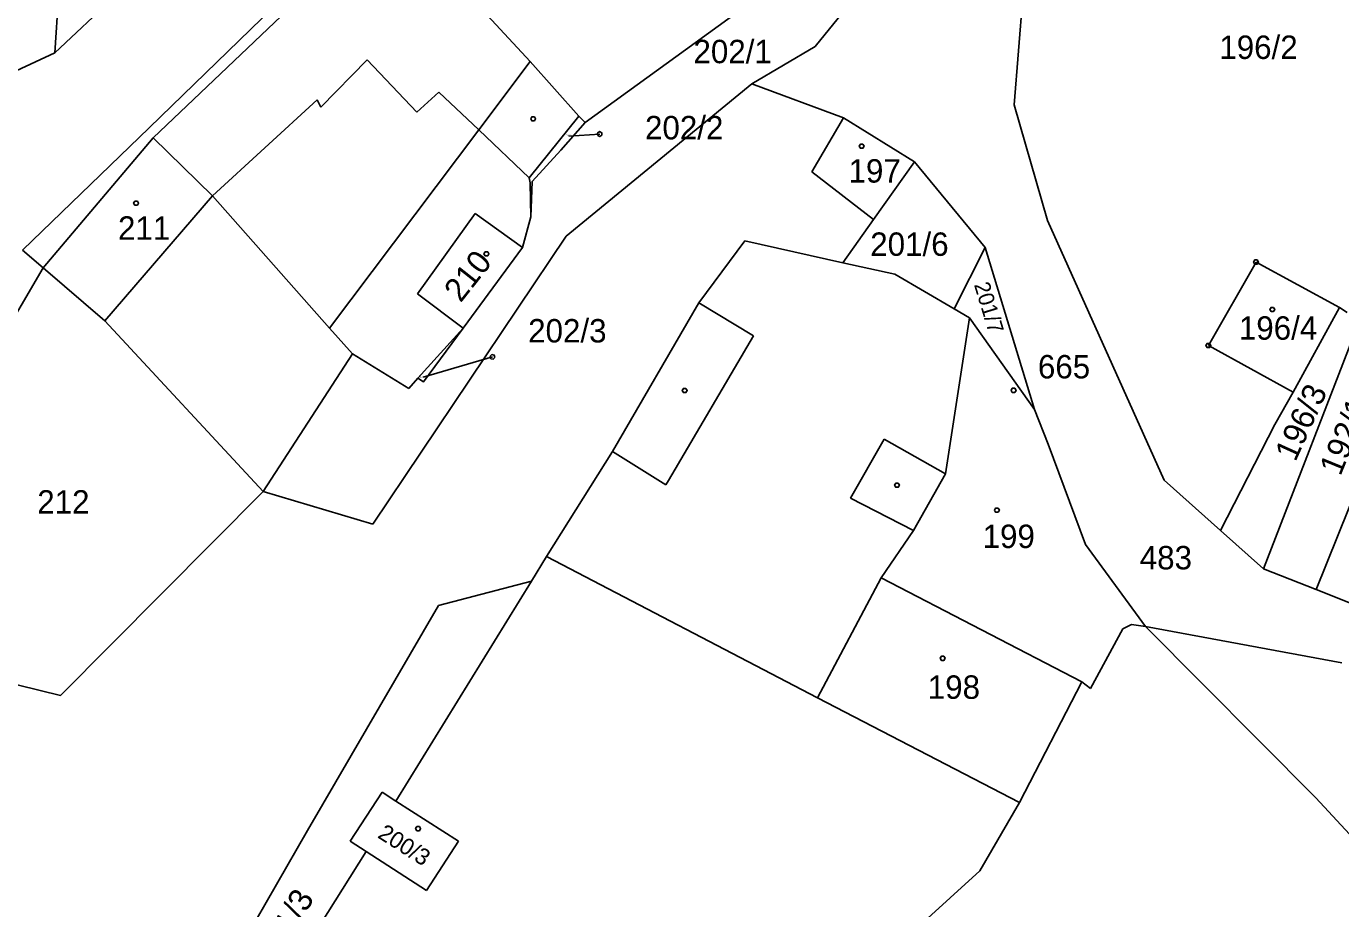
# Model space of a CAD drawing. Extents: x -634640 to -629202, y -1196156 to -1190068.
# Drawn here: x -631585.1 to -631489.7, y -1192866.1 to -1192802 of the extents above; entities that cross this region are included whole.
import ezdxf

# ---------------------------------------------------------------- set-up
doc = ezdxf.new("R2010")
doc.units = 0
for name, color, linetype in [('Vrstva 1', 7, 'Continuous'), ('Vrstva 2', 7, 'Continuous'), ('Vrstva 3', 7, 'Continuous'), ('Vrstva 4', 7, 'Continuous'), ('Vrstva 5', 7, 'Continuous'), ('Vrstva 7', 7, 'Continuous'), ('Vrstva 8', 7, 'Continuous')]:
    doc.layers.add(name, color=color, linetype=linetype)

msp = doc.modelspace()

# ---------------------------------------------------------------- linework, layer by layer
at = {"layer": 'Vrstva 1'}
for p, q in [((-631583.01, -1192803.9), (-631580.81, -1192771.97)), ((-631576.15, -1192809.34), (-631541.58, -1192775.76)), ((-631516.38, -1192789.3), (-631527.81, -1192803.43)), ((-631571.55, -1192793.1), (-631583.01, -1192803.9)), ((-631575.85, -1192810.06), (-631558.85, -1192793.87)), ((-631513.36, -1192807.68), (-631512.6, -1192797.92)), ((-631548.5, -1192804.53), (-631553.28, -1192799.36)), ((-631544.5, -1192808.96), (-631533.46, -1192800.95)), ((-631527.81, -1192803.43), (-631532.4, -1192806.15)), ((-631583.01, -1192803.9), (-631591.61, -1192807.9)), ((-631548.5, -1192804.53), (-631552.23, -1192809.49)), ((-631544.96, -1192808.49), (-631548.5, -1192804.53)), ((-631545.88, -1192817.22), (-631532.4, -1192806.15)), ((-631532.4, -1192806.15), (-631525.75, -1192808.62)), ((-631510.95, -1192816.08), (-631513.36, -1192807.68)), ((-631548.56, -1192812.97), (-631544.96, -1192808.49)), ((-631544.96, -1192808.49), (-631544.5, -1192808.96)), ((-631528.06, -1192812.54), (-631525.75, -1192808.62)), ((-631525.75, -1192808.62), (-631520.6, -1192811.81)), ((-631585.34, -1192818.22), (-631576.15, -1192809.34)), ((-631552.23, -1192809.49), (-631563.05, -1192823.88)), ((-631583.85, -1192819.52), (-631575.85, -1192810.06)), ((-631571.56, -1192814.28), (-631575.85, -1192810.06)), ((-631520.6, -1192811.81), (-631523.58, -1192816)), ((-631520.6, -1192811.81), (-631515.46, -1192818.03)), ((-631548.49, -1192813.33), (-631548.56, -1192812.97)), ((-631548.46, -1192815.81), (-631548.49, -1192813.33)), ((-631523.58, -1192816), (-631528.06, -1192812.54)), ((-631563.05, -1192823.88), (-631571.56, -1192814.28)), ((-631549.06, -1192818.04), (-631548.46, -1192815.81)), ((-631525.81, -1192819.14), (-631523.58, -1192816)), ((-631502.47, -1192834.94), (-631510.95, -1192816.08)), ((-631559.92, -1192838.12), (-631545.88, -1192817.22)), ((-631553.36, -1192823.89), (-631549.06, -1192818.04)), ((-631536.26, -1192822.05), (-631532.91, -1192817.55)), ((-631532.91, -1192817.55), (-631525.81, -1192819.14)), ((-631517.72, -1192822.49), (-631515.46, -1192818.03)), ((-631515.46, -1192818.03), (-631511.89, -1192829.79)), ((-631583.85, -1192819.52), (-631585.34, -1192818.22)), ((-631499.27, -1192825.15), (-631495.81, -1192819.09)), ((-631495.81, -1192819.09), (-631489.75, -1192822.4)), ((-631588.86, -1192828.06), (-631583.85, -1192819.52)), ((-631579.37, -1192823.37), (-631583.85, -1192819.52)), ((-631525.81, -1192819.14), (-631522.03, -1192819.98)), ((-631522.03, -1192819.98), (-631517.72, -1192822.49)), ((-631542.52, -1192832.86), (-631536.26, -1192822.05)), ((-631517.72, -1192822.49), (-631516.62, -1192823.13)), ((-631493.12, -1192828.53), (-631489.75, -1192822.4)), ((-631489.75, -1192822.4), (-631489.2, -1192822.75)), ((-631567.88, -1192835.75), (-631579.37, -1192823.37)), ((-631561.39, -1192825.75), (-631563.05, -1192823.88)), ((-631556.64, -1192827.53), (-631553.36, -1192823.89)), ((-631516.62, -1192823.13), (-631518.36, -1192834.46)), ((-631516.62, -1192823.13), (-631511.89, -1192829.79)), ((-631495.28, -1192841.36), (-631488.24, -1192823.16)), ((-631567.88, -1192835.75), (-631561.39, -1192825.75)), ((-631561.39, -1192825.75), (-631557.31, -1192828.27)), ((-631493.12, -1192828.53), (-631499.27, -1192825.15)), ((-631484.24, -1192824.88), (-631491.45, -1192842.88)), ((-631557.31, -1192828.27), (-631556.64, -1192827.53)), ((-631494.45, -1192830.88), (-631493.12, -1192828.53)), ((-631511.89, -1192829.79), (-631510.89, -1192832.32)), ((-631498.38, -1192838.59), (-631494.45, -1192830.88)), ((-631510.89, -1192832.32), (-631508.18, -1192839.61)), ((-631547.3, -1192840.48), (-631542.52, -1192832.86)), ((-631518.36, -1192834.46), (-631520.67, -1192838.59)), ((-631498.38, -1192838.59), (-631502.47, -1192834.94)), ((-631582.58, -1192850.56), (-631567.88, -1192835.75)), ((-631567.88, -1192835.75), (-631559.92, -1192838.12)), ((-631520.67, -1192838.59), (-631523.02, -1192842.03)), ((-631495.28, -1192841.36), (-631498.38, -1192838.59)), ((-631508.18, -1192839.61), (-631503.84, -1192845.57)), ((-631548.4, -1192842.27), (-631547.3, -1192840.48)), ((-631527.64, -1192850.75), (-631547.3, -1192840.48)), ((-631523.02, -1192842.03), (-631508.46, -1192849.58)), ((-631491.45, -1192842.88), (-631495.28, -1192841.36)), ((-631558.24, -1192858.25), (-631548.4, -1192842.27)), ((-631548.4, -1192842.27), (-631555.14, -1192844.03)), ((-631464.48, -1192853.54), (-631491.45, -1192842.88)), ((-631555.14, -1192844.03), (-631564.65, -1192860.37)), ((-631507.83, -1192850.07), (-631505.49, -1192845.72)), ((-631505.49, -1192845.72), (-631504.86, -1192845.42)), ((-631504.86, -1192845.42), (-631503.84, -1192845.57)), ((-631503.84, -1192845.57), (-631489.58, -1192848.19)), ((-631491.47, -1192858), (-631503.84, -1192845.57)), ((-631593.6, -1192847.88), (-631582.58, -1192850.56)), ((-631512.97, -1192858.34), (-631508.46, -1192849.58)), ((-631508.46, -1192849.58), (-631507.83, -1192850.07)), ((-631512.97, -1192858.34), (-631527.64, -1192850.75)), ((-631561.55, -1192861.14), (-631559.23, -1192857.6)), ((-631559.23, -1192857.6), (-631558.24, -1192858.25)), ((-631553.69, -1192861.15), (-631558.24, -1192858.25)), ((-631484.63, -1192865.42), (-631491.47, -1192858)), ((-631515.85, -1192863.31), (-631512.97, -1192858.34)), ((-631564.65, -1192860.37), (-631569.79, -1192869.32)), ((-631584.97, -1192900.87), (-631560.39, -1192861.89)), ((-631561.55, -1192861.14), (-631560.39, -1192861.89)), ((-631560.39, -1192861.89), (-631556.03, -1192864.73)), ((-631556.03, -1192864.73), (-631553.69, -1192861.15)), ((-631520.17, -1192867.23), (-631515.85, -1192863.31))]:
    msp.add_line(p, q, dxfattribs=at)
for points in [[(-631548.46, -1192815.81), (-631548.34, -1192813.25), (-631546.28, -1192810.97), (-631544.5, -1192808.96)], [(-631556.64, -1192827.53), (-631556.24, -1192827.8), (-631553.36, -1192823.89)]]:
    msp.add_lwpolyline(points, dxfattribs=at)
at = {"layer": 'Vrstva 3'}
msp.add_lwpolyline([(-631514.53, -1192836.96), (-631514.44, -1192837.11), (-631514.53, -1192837.26), (-631514.71, -1192837.26), (-631514.8, -1192837.11), (-631514.71, -1192836.96), (-631514.53, -1192836.96)], dxfattribs=at)
at = {"layer": 'Vrstva 4'}
for p, q in [((-631560.33, -1192804.4), (-631563.69, -1192807.84)), ((-631556.73, -1192808.2), (-631560.33, -1192804.4)), ((-631563.95, -1192807.32), (-631571.56, -1192814.28)), ((-631563.69, -1192807.84), (-631563.95, -1192807.32)), ((-631555.12, -1192806.75), (-631556.73, -1192808.2)), ((-631552.23, -1192809.49), (-631555.12, -1192806.75)), ((-631552.23, -1192809.49), (-631548.56, -1192812.97)), ((-631571.56, -1192814.28), (-631579.37, -1192823.37)), ((-631552.5, -1192815.56), (-631556.68, -1192821.41)), ((-631549.06, -1192818.04), (-631552.5, -1192815.56)), ((-631556.68, -1192821.41), (-631553.36, -1192823.89)), ((-631536.26, -1192822.05), (-631532.29, -1192824.44)), ((-631532.29, -1192824.44), (-631538.45, -1192834.95)), ((-631525.25, -1192836.23), (-631522.8, -1192831.96)), ((-631522.8, -1192831.96), (-631518.36, -1192834.46)), ((-631538.64, -1192835.28), (-631542.52, -1192832.86)), ((-631538.45, -1192834.95), (-631538.64, -1192835.28)), ((-631520.67, -1192838.59), (-631525.25, -1192836.23)), ((-631523.02, -1192842.03), (-631527.64, -1192850.75))]:
    msp.add_line(p, q, dxfattribs=at)
at = {"layer": 'Vrstva 5'}
for points in [[(-631548.19, -1192808.54), (-631548.1, -1192808.69), (-631548.19, -1192808.84), (-631548.37, -1192808.84), (-631548.46, -1192808.69), (-631548.37, -1192808.54), (-631548.19, -1192808.54)], [(-631524.35, -1192810.53), (-631524.26, -1192810.68), (-631524.35, -1192810.83), (-631524.53, -1192810.83), (-631524.62, -1192810.68), (-631524.53, -1192810.53), (-631524.35, -1192810.53)], [(-631577.01, -1192814.67), (-631576.92, -1192814.82), (-631577.01, -1192814.97), (-631577.19, -1192814.97), (-631577.28, -1192814.82), (-631577.19, -1192814.67), (-631577.01, -1192814.67)], [(-631551.58, -1192818.34), (-631551.49, -1192818.49), (-631551.58, -1192818.64), (-631551.76, -1192818.64), (-631551.85, -1192818.49), (-631551.76, -1192818.34), (-631551.58, -1192818.34)], [(-631494.54, -1192822.38), (-631494.45, -1192822.53), (-631494.54, -1192822.68), (-631494.72, -1192822.68), (-631494.81, -1192822.53), (-631494.72, -1192822.38), (-631494.54, -1192822.38)], [(-631537.19, -1192828.27), (-631537.1, -1192828.42), (-631537.19, -1192828.57), (-631537.37, -1192828.57), (-631537.46, -1192828.42), (-631537.37, -1192828.27), (-631537.19, -1192828.27)], [(-631521.78, -1192835.15), (-631521.69, -1192835.3), (-631521.78, -1192835.45), (-631521.96, -1192835.45), (-631522.05, -1192835.3), (-631521.96, -1192835.15), (-631521.78, -1192835.15)], [(-631518.47, -1192847.72), (-631518.38, -1192847.87), (-631518.47, -1192848.02), (-631518.65, -1192848.02), (-631518.74, -1192847.87), (-631518.65, -1192847.72), (-631518.47, -1192847.72)], [(-631556.54, -1192860.09), (-631556.45, -1192860.24), (-631556.54, -1192860.39), (-631556.72, -1192860.39), (-631556.81, -1192860.24), (-631556.72, -1192860.09), (-631556.54, -1192860.09)]]:
    msp.add_lwpolyline(points, dxfattribs=at)
at = {"layer": 'Vrstva 7'}
for p, q in [((-631545.68, -1192809.94), (-631543.45, -1192809.8)), ((-631556.26, -1192827.46), (-631551.23, -1192825.98))]:
    msp.add_line(p, q, dxfattribs=at)
for points in [[(-631543.295, -1192809.88), (-631543.438, -1192809.98), (-631543.594, -1192809.899), (-631543.605, -1192809.72), (-631543.462, -1192809.62), (-631543.306, -1192809.701), (-631543.295, -1192809.88)], [(-631551.061, -1192826.024), (-631551.179, -1192826.153), (-631551.349, -1192826.109), (-631551.399, -1192825.936), (-631551.281, -1192825.807), (-631551.111, -1192825.851), (-631551.061, -1192826.024)]]:
    msp.add_lwpolyline(points, dxfattribs=at)
at = {"layer": 'Vrstva 8'}
for points in [[(-631495.72, -1192818.94), (-631495.63, -1192819.09), (-631495.72, -1192819.24), (-631495.9, -1192819.24), (-631495.99, -1192819.09), (-631495.9, -1192818.94), (-631495.72, -1192818.94)], [(-631499.18, -1192825), (-631499.09, -1192825.15), (-631499.18, -1192825.3), (-631499.36, -1192825.3), (-631499.45, -1192825.15), (-631499.36, -1192825), (-631499.18, -1192825)], [(-631513.32, -1192828.26), (-631513.23, -1192828.41), (-631513.32, -1192828.56), (-631513.5, -1192828.56), (-631513.59, -1192828.41), (-631513.5, -1192828.26), (-631513.32, -1192828.26)]]:
    msp.add_lwpolyline(points, dxfattribs=at)

# ---------------------------------------------------------------- texts
at = {"layer": 'Vrstva 2'}
for s, height, p in [('202/1', 1.7, (-631536.644, -1192804.65)), ('196/2', 1.7, (-631498.477, -1192804.34)), ('202/2', 0.1, (-631545.91, -1192809.94)), ('197', 1.7, (-631525.387, -1192813.32)), ('211', 1.7, (-631578.413, -1192817.47)), ('201/6', 1.7, (-631523.813, -1192818.64)), ('196/4', 1.7, (-631497.057, -1192824.73)), ('202/3', 0.1, (-631556.49, -1192827.46)), ('212', 1.7, (-631584.273, -1192837.36)), ('199', 1.7, (-631515.657, -1192839.86)), ('483', 1.7, (-631504.253, -1192841.41)), ('198', 1.7, (-631519.637, -1192850.81))]:
    msp.add_text(s, height=height, dxfattribs=at).set_placement(p)
for s, height, rotation, p in [('210', 1.7, 51.68079, (-631553.543, -1192822.094)), ('201/7', 1.14, 286.93726, (-631516.292, -1192820.729)), ('196/3', 1.7, 65.60367, (-631492.958, -1192833.652)), ('192/1', 1.7, 67.72361, (-631489.691, -1192834.687)), ('200/3', 1.2, 327.61727, (-631559.638, -1192860.85)), ('201/3', 1.7, 59.93139, (-631566.981, -1192870.205))]:
    msp.add_text(s, height=height, rotation=rotation, dxfattribs=at).set_placement(p)
at = {"layer": 'Vrstva 7'}
for s, p in [('202/2', (-631540.162, -1192810.18)), ('202/3', (-631548.642, -1192824.93))]:
    msp.add_text(s, height=1.7, dxfattribs=at).set_placement(p)
at = {"layer": 'Vrstva 8'}
msp.add_text('665', height=1.7, dxfattribs=at).set_placement((-631511.643, -1192827.54))

doc.saveas('drawing.dxf')
